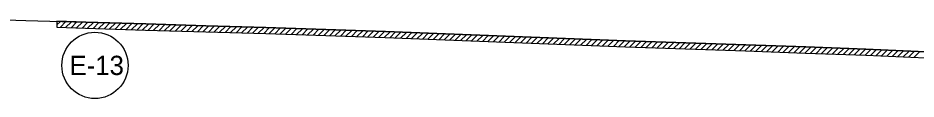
# Model space of a CAD drawing. Extents: x 976877 to 983987, y 1525984 to 1526526.
# Drawn here: x 977339.9 to 977564, y 1526487.3 to 1526507.3 of the extents above; entities that cross this region are included whole.
import ezdxf

# ---------------------------------------------------------------- set-up
doc = ezdxf.new("R2010")
doc.units = 0
doc.layers.add('R_Erosion', color=7, linetype='Continuous')
doc.layers.add('R_No Plot', color=7, linetype='Continuous')

msp = doc.modelspace()

# ---------------------------------------------------------------- linework, layer by layer
at = {"layer": 'R_Erosion'}
for p, q in [((977349.59, 1526506.56), (977349.55, 1526505.06)), ((977349.57, 1526505.64), (977350.46, 1526506.54)), ((977356.78, 1526506.35), (977349.59, 1526506.56)), ((977350.38, 1526505.04), (977351.83, 1526506.5)), ((977351.75, 1526505), (977353.21, 1526506.46)), ((977353.12, 1526504.96), (977354.58, 1526506.42)), ((977354.5, 1526504.92), (977355.95, 1526506.37)), ((977355.87, 1526504.88), (977357.33, 1526506.33)), ((977371.77, 1526505.89), (977356.78, 1526506.35)), ((977357.24, 1526504.84), (977358.7, 1526506.29)), ((977358.61, 1526504.79), (977360.07, 1526506.25)), ((977359.99, 1526504.75), (977361.44, 1526506.21)), ((977361.36, 1526504.71), (977362.81, 1526506.16)), ((977362.73, 1526504.67), (977364.19, 1526506.12)), ((977364.1, 1526504.62), (977365.56, 1526506.08)), ((977365.47, 1526504.58), (977366.93, 1526506.04)), ((977366.85, 1526504.54), (977368.3, 1526505.99)), ((977368.22, 1526504.5), (977369.67, 1526505.95)), ((977369.59, 1526504.45), (977371.05, 1526505.91)), ((977370.96, 1526504.41), (977372.42, 1526505.87)), ((977372.33, 1526504.37), (977373.79, 1526505.82)), ((977373.7, 1526504.32), (977375.16, 1526505.78)), ((977375.07, 1526504.28), (977376.53, 1526505.73)), ((977376.44, 1526504.24), (977377.9, 1526505.69)), ((977377.81, 1526504.19), (977379.27, 1526505.65)), ((977379.18, 1526504.15), (977380.64, 1526505.6)), ((977380.55, 1526504.1), (977382.01, 1526505.56)), ((977381.92, 1526504.06), (977383.38, 1526505.51)), ((977383.29, 1526504.02), (977384.75, 1526505.47)), ((977384.66, 1526503.97), (977386.12, 1526505.43)), ((977386.04, 1526503.93), (977387.49, 1526505.39)), ((977387.41, 1526503.89), (977388.87, 1526505.35)), ((977388.79, 1526503.85), (977390.25, 1526505.32)), ((977390.17, 1526503.82), (977391.63, 1526505.28)), ((977391.55, 1526503.78), (977393.01, 1526505.25)), ((977392.93, 1526503.75), (977394.39, 1526505.21)), ((977394.3, 1526503.71), (977395.77, 1526505.18)), ((977395.68, 1526503.68), (977397.15, 1526505.14)), ((977397.06, 1526503.64), (977398.52, 1526505.1)), ((977398.44, 1526503.61), (977399.9, 1526505.07)), ((977399.82, 1526503.57), (977401.28, 1526505.03)), ((977401.2, 1526503.54), (977402.65, 1526504.99)), ((977402.57, 1526503.49), (977404.02, 1526504.95)), ((977403.94, 1526503.45), (977405.39, 1526504.9)), ((977405.31, 1526503.4), (977406.76, 1526504.85)), ((977406.67, 1526503.35), (977408.13, 1526504.81)), ((977408.04, 1526503.31), (977409.49, 1526504.76)), ((977409.41, 1526503.26), (977410.86, 1526504.71)), ((977410.78, 1526503.22), (977412.23, 1526504.67)), ((977412.15, 1526503.17), (977413.6, 1526504.62)), ((977413.51, 1526503.12), (977414.97, 1526504.57)), ((977414.88, 1526503.08), (977416.33, 1526504.53)), ((977416.25, 1526503.03), (977417.7, 1526504.48)), ((977417.62, 1526502.98), (977419.07, 1526504.44)), ((977418.99, 1526502.94), (977420.44, 1526504.39)), ((977420.35, 1526502.89), (977421.81, 1526504.34)), ((977421.72, 1526502.85), (977423.17, 1526504.3)), ((977423.09, 1526502.8), (977424.54, 1526504.25)), ((977424.46, 1526502.76), (977425.91, 1526504.21)), ((977425.83, 1526502.71), (977427.28, 1526504.16)), ((977427.2, 1526502.66), (977428.65, 1526504.12)), ((977428.56, 1526502.62), (977430.02, 1526504.07)), ((977429.93, 1526502.57), (977431.39, 1526504.02)), ((977431.3, 1526502.53), (977432.75, 1526503.97)), ((977432.66, 1526502.47), (977434.11, 1526503.92)), ((977434.02, 1526502.42), (977435.46, 1526503.86)), ((977435.38, 1526502.36), (977436.82, 1526503.81)), ((977436.74, 1526502.31), (977438.18, 1526503.75)), ((977438.1, 1526502.25), (977439.54, 1526503.7)), ((977439.46, 1526502.2), (977440.9, 1526503.64)), ((977440.82, 1526502.14), (977442.26, 1526503.59)), ((977442.18, 1526502.09), (977443.62, 1526503.53)), ((977443.54, 1526502.03), (977444.98, 1526503.48)), ((977444.9, 1526501.98), (977446.34, 1526503.42)), ((977446.25, 1526501.92), (977447.7, 1526503.37)), ((977447.62, 1526501.87), (977449.06, 1526503.32)), ((977448.98, 1526501.82), (977450.42, 1526503.26)), ((977450.34, 1526501.77), (977451.79, 1526503.21)), ((977451.7, 1526501.72), (977453.15, 1526503.16)), ((977453.07, 1526501.66), (977454.51, 1526503.11)), ((977454.43, 1526501.61), (977455.87, 1526503.06)), ((977455.79, 1526501.56), (977457.24, 1526503.01)), ((977457.15, 1526501.51), (977458.6, 1526502.95)), ((977458.52, 1526501.46), (977459.96, 1526502.9)), ((977459.88, 1526501.4), (977461.32, 1526502.85)), ((977461.24, 1526501.35), (977462.68, 1526502.8)), ((977462.6, 1526501.3), (977464.04, 1526502.74)), ((977463.96, 1526501.24), (977465.4, 1526502.69)), ((977465.32, 1526501.19), (977466.76, 1526502.63)), ((977466.68, 1526501.14), (977468.12, 1526502.58)), ((977468.04, 1526501.08), (977469.48, 1526502.53)), ((977469.4, 1526501.03), (977470.84, 1526502.47)), ((977470.76, 1526500.97), (977472.2, 1526502.42)), ((977472.12, 1526500.92), (977473.56, 1526502.36)), ((977473.48, 1526500.86), (977474.92, 1526502.31)), ((977474.84, 1526500.81), (977476.28, 1526502.25)), ((977476.2, 1526500.76), (977477.65, 1526502.2)), ((977477.56, 1526500.71), (977479.01, 1526502.16)), ((977478.93, 1526500.66), (977480.38, 1526502.11)), ((977480.3, 1526500.61), (977481.75, 1526502.06)), ((977481.66, 1526500.56), (977483.11, 1526502.01)), ((977483.03, 1526500.51), (977484.48, 1526501.96)), ((977484.39, 1526500.46), (977485.84, 1526501.91)), ((977485.76, 1526500.41), (977487.21, 1526501.86)), ((977487.12, 1526500.37), (977488.57, 1526501.82)), ((977488.49, 1526500.32), (977489.94, 1526501.77)), ((977489.85, 1526500.27), (977491.3, 1526501.72)), ((977491.22, 1526500.22), (977492.67, 1526501.67)), ((977492.59, 1526500.17), (977494.04, 1526501.62)), ((977493.95, 1526500.12), (977495.4, 1526501.57)), ((977495.32, 1526500.07), (977496.77, 1526501.52)), ((977496.68, 1526500.02), (977498.13, 1526501.47)), ((977498.05, 1526499.98), (977499.5, 1526501.43)), ((977499.41, 1526499.93), (977500.86, 1526501.38)), ((977500.78, 1526499.88), (977502.23, 1526501.33)), ((977502.14, 1526499.83), (977503.59, 1526501.28)), ((977503.51, 1526499.78), (977504.96, 1526501.23)), ((977504.88, 1526499.73), (977506.32, 1526501.18)), ((977506.24, 1526499.68), (977507.69, 1526501.14)), ((977507.61, 1526499.64), (977509.06, 1526501.09)), ((977508.98, 1526499.59), (977510.43, 1526501.05)), ((977510.35, 1526499.55), (977511.8, 1526501)), ((977511.72, 1526499.5), (977513.17, 1526500.96)), ((977513.09, 1526499.46), (977514.54, 1526500.91)), ((977514.46, 1526499.42), (977515.91, 1526500.87)), ((977515.83, 1526499.37), (977517.28, 1526500.82)), ((977517.2, 1526499.33), (977518.65, 1526500.78)), ((977518.57, 1526499.28), (977520.02, 1526500.74)), ((977519.94, 1526499.24), (977521.39, 1526500.69)), ((977521.31, 1526499.19), (977522.76, 1526500.64)), ((977536.55, 1526500.16), (977521.56, 1526500.68)), ((977522.67, 1526499.15), (977524.12, 1526500.6)), ((977524.04, 1526499.1), (977525.49, 1526500.55)), ((977525.41, 1526499.05), (977526.86, 1526500.5)), ((977526.77, 1526499), (977528.22, 1526500.45)), ((977528.14, 1526498.96), (977529.59, 1526500.41)), ((977529.51, 1526498.91), (977530.96, 1526500.36)), ((977530.87, 1526498.86), (977532.32, 1526500.31)), ((977532.24, 1526498.81), (977533.69, 1526500.26)), ((977533.61, 1526498.77), (977535.06, 1526500.22)), ((977534.97, 1526498.72), (977536.42, 1526500.17)), ((977536.34, 1526498.67), (977537.79, 1526500.12)), ((977551.53, 1526499.62), (977536.55, 1526500.16)), ((977537.7, 1526498.62), (977539.15, 1526500.07)), ((977539.07, 1526498.57), (977540.52, 1526500.02)), ((977540.43, 1526498.52), (977541.88, 1526499.97)), ((977541.8, 1526498.47), (977543.25, 1526499.92)), ((977543.16, 1526498.42), (977544.61, 1526499.87)), ((977544.53, 1526498.37), (977545.98, 1526499.82)), ((977545.89, 1526498.32), (977547.34, 1526499.77)), ((977547.26, 1526498.27), (977548.7, 1526499.72)), ((977548.62, 1526498.22), (977550.07, 1526499.67)), ((977549.98, 1526498.17), (977551.43, 1526499.62)), ((977551.35, 1526498.12), (977552.79, 1526499.56)), ((977552.71, 1526498.07), (977554.15, 1526499.51)), ((977554.06, 1526498.01), (977555.5, 1526499.45)), ((977555.42, 1526497.95), (977556.86, 1526499.39)), ((977556.78, 1526497.89), (977558.22, 1526499.33)), ((977558.13, 1526497.84), (977559.57, 1526499.28)), ((977559.49, 1526497.78), (977560.93, 1526499.22)), ((977560.85, 1526497.72), (977562.29, 1526499.16)), ((977562.2, 1526497.66), (977563.64, 1526499.1)), ((977563.56, 1526497.61), (977565, 1526499.05))]:
    msp.add_line(p, q, dxfattribs=at)
for points in [[(977401.76, 1526505.02), (977386.77, 1526505.41), (977371.78, 1526505.89)], [(977349.55, 1526505.06), (977356.74, 1526504.85), (977371.73, 1526504.39), (977386.72, 1526503.91)], [(977349.55, 1526505.06), (977356.74, 1526504.85), (977371.73, 1526504.39), (977386.72, 1526503.91)], [(977386.73, 1526503.91), (977401.72, 1526503.52), (977416.7, 1526503.01)], [(977386.73, 1526503.91), (977401.72, 1526503.52), (977416.7, 1526503.01)], [(977431.59, 1526504.02), (977416.75, 1526504.51), (977401.77, 1526505.02)], [(977461.57, 1526502.84), (977446.58, 1526503.41), (977431.6, 1526504.02)], [(977416.7, 1526503.01), (977431.54, 1526502.52), (977446.52, 1526501.91)], [(977416.7, 1526503.01), (977431.54, 1526502.52), (977446.52, 1526501.91)], [(977446.52, 1526501.91), (977461.51, 1526501.34), (977476.5, 1526500.74)], [(977446.52, 1526501.91), (977461.51, 1526501.34), (977476.5, 1526500.74)], [(977491.55, 1526501.71), (977476.56, 1526502.24), (977461.57, 1526502.84)], [(977521.55, 1526500.68), (977506.54, 1526501.17), (977491.55, 1526501.71)], [(977476.51, 1526500.74), (977491.5, 1526500.21), (977506.49, 1526499.67)], [(977476.51, 1526500.74), (977491.5, 1526500.21), (977506.49, 1526499.67)], [(977506.49, 1526499.67), (977521.51, 1526499.19), (977536.49, 1526498.66), (977551.48, 1526498.12), (977566.46, 1526497.48)], [(977506.49, 1526499.67), (977521.51, 1526499.19), (977536.49, 1526498.66), (977551.48, 1526498.12), (977566.46, 1526497.48)], [(977581.51, 1526498.47), (977566.52, 1526498.98), (977551.54, 1526499.62)]]:
    msp.add_lwpolyline(points, dxfattribs=at)
msp.add_circle((977359.07, 1526495.58), 8.26, dxfattribs=at)
for centre, start, end in [((977356.74, 1526504.85), 88.2312, 88.2962), ((977371.73, 1526504.39), 88.1625, 88.2312), ((977386.77, 1526505.41), 268.1625, 268.5331), ((977386.77, 1526505.41), 268.1625, 268.5331), ((977401.72, 1526503.52), 88.0593, 88.5331), ((977431.54, 1526502.52), 87.6847, 88.0817), ((977416.75, 1526504.51), 268.0593, 268.0817), ((977446.58, 1526503.41), 267.6847, 267.8222), ((977446.58, 1526503.41), 267.6847, 267.8222), ((977461.51, 1526501.34), 87.7152, 87.8222), ((977491.5, 1526500.21), 87.9561, 87.9599), ((977476.56, 1526502.24), 267.7152, 267.9599), ((977476.56, 1526502.24), 267.7152, 267.9599), ((977506.54, 1526501.17), 267.9561, 268.1347), ((977521.51, 1526499.19), 88.0095, 88.1347), ((977536.49, 1526498.66), 87.9101, 88.0095), ((977551.48, 1526498.12), 87.5698, 87.9101)]:
    msp.add_arc(centre, 1.5, start, end, dxfattribs=at)
at = {"layer": 'R_No Plot'}
msp.add_lwpolyline([(977326.73, 1526507.26), (977341.79, 1526506.8), (977356.78, 1526506.35), (977371.77, 1526505.89), (977386.77, 1526505.41), (977401.76, 1526505.02), (977416.75, 1526504.51), (977431.59, 1526504.02), (977446.58, 1526503.41), (977461.57, 1526502.84), (977476.56, 1526502.24), (977491.55, 1526501.71), (977506.54, 1526501.17), (977521.56, 1526500.68), (977536.55, 1526500.16), (977551.54, 1526499.62), (977566.52, 1526498.98)], dxfattribs=at)
msp.add_circle((977359.07, 1526495.58), 8.26, dxfattribs=at)

# ---------------------------------------------------------------- texts
at = {"layer": 'R_Erosion'}
msp.add_text('E-13', height=4.8, dxfattribs=at).set_placement((977352.74, 1526493.18))

doc.saveas('drawing.dxf')
